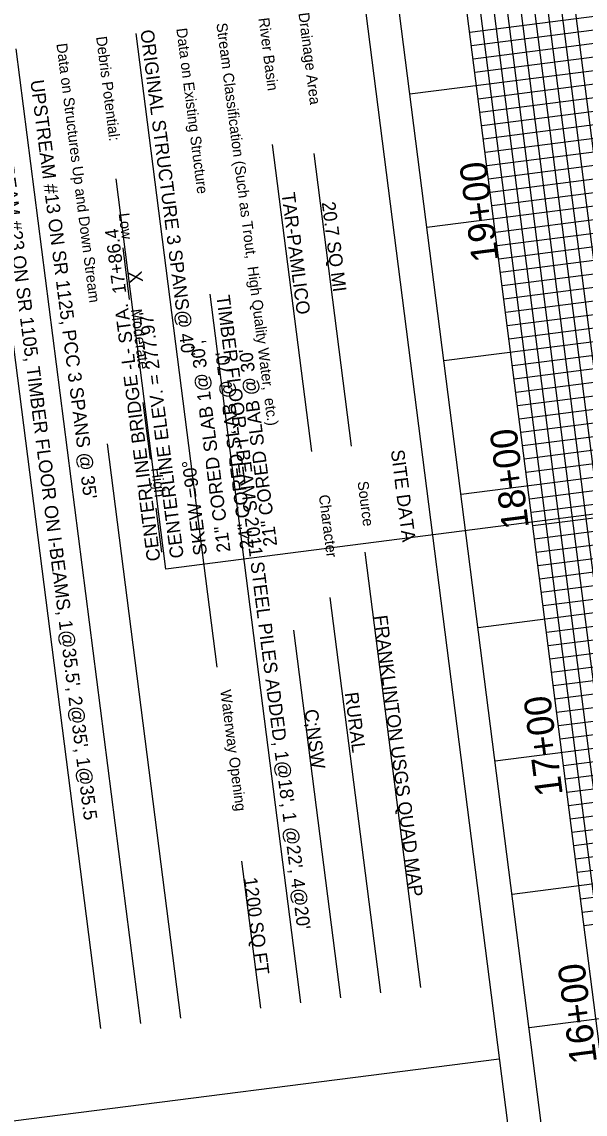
# Model space of a CAD drawing. Extents: x 2166991 to 2168413, y 842679 to 844296.
# Drawn here: x 2167468.2 to 2167677.7, y 843150.5 to 843556.7 of the extents above; entities that cross this region are included whole.
import ezdxf

# ---------------------------------------------------------------- set-up
doc = ezdxf.new("R2010")
doc.units = 0
for name, color, linetype in [('Prop Plan Preparation Cover Label', 7, 'Continuous'), ('Prop Plan Preparation Drainage Notes Label', 7, 'Continuous'), ('Prop Plan Preparation Sheet Bridge Report Limited Study CELL', 7, 'Continuous'), ('Prop Plan Preparation Station Label', 7, 'Continuous')]:
    doc.layers.add(name, color=color, linetype=linetype)

msp = doc.modelspace()

# ---------------------------------------------------------------- linework, layer by layer
at = {"layer": 'Prop Plan Preparation Drainage Notes Label'}
for p, q in [((2167521.8, 843353.19), (2167503.28, 843498.24)), ((2167765.56, 843384.32), (2167521.8, 843353.19))]:
    msp.add_line(p, q, dxfattribs=at)
at = {"layer": 'Prop Plan Preparation Sheet Bridge Report Limited Study CELL'}
for p, q in [((2167538.09, 844014.21), (2167699.63, 842749.49)), ((2167538.09, 844014.21), (2167699.63, 842749.49)), ((2167735.56, 842764.16), (2167577.19, 844004.08)), ((2167710.76, 842760.99), (2167552.39, 844000.92)), ((2167752.23, 842791.49), (2167600.19, 843981.82)), ((2167757.19, 842792.12), (2167605.15, 843982.45)), ((2167762.15, 842792.76), (2167610.11, 843983.09)), ((2167767.11, 842793.39), (2167615.07, 843983.72)), ((2167772.07, 842794.02), (2167620.03, 843984.35)), ((2167737.35, 842789.59), (2167585.31, 843979.92)), ((2167742.31, 842790.22), (2167590.27, 843980.55)), ((2167747.27, 842790.86), (2167595.23, 843981.18)), ((2168130.81, 843616.1), (2167634.84, 843552.75)), ((2168131.44, 843611.14), (2167635.47, 843547.79)), ((2168132.07, 843606.18), (2167636.1, 843542.83)), ((2168132.71, 843601.22), (2167636.74, 843537.87)), ((2168133.34, 843596.26), (2167612.57, 843529.74)), ((2168133.97, 843591.3), (2167638, 843527.95)), ((2168134.61, 843586.34), (2167638.64, 843522.99)), ((2168135.24, 843581.38), (2167639.27, 843518.03)), ((2168135.87, 843576.42), (2167639.9, 843513.07)), ((2168136.51, 843571.46), (2167640.54, 843508.11)), ((2168137.14, 843566.5), (2167641.17, 843503.15)), ((2168137.77, 843561.54), (2167641.8, 843498.19)), ((2168138.41, 843556.58), (2167642.44, 843493.23)), ((2167540.89, 843316.64), (2167510.79, 843552.29)), ((2168139.04, 843551.62), (2167643.07, 843488.27)), ((2167497.56, 843182.31), (2167451.28, 843544.69)), ((2167512.44, 843184.21), (2167466.16, 843546.59)), ((2168139.68, 843546.66), (2167618.91, 843480.15)), ((2168140.31, 843541.7), (2167644.34, 843478.35)), ((2168140.94, 843536.74), (2167644.97, 843473.39)), ((2168141.58, 843531.78), (2167645.61, 843468.43)), ((2168142.21, 843526.83), (2167646.24, 843463.47)), ((2168142.84, 843521.87), (2167646.87, 843458.52)), ((2168143.48, 843516.91), (2167647.51, 843453.56)), ((2167576.04, 843396.95), (2167561.47, 843511.05)), ((2168144.11, 843511.95), (2167648.14, 843448.6)), ((2167590.88, 843398.85), (2167576.97, 843507.77)), ((2168144.74, 843506.99), (2167648.77, 843443.64)), ((2168145.38, 843502.03), (2167649.41, 843438.68)), ((2168146.01, 843497.07), (2167625.24, 843430.55)), ((2168146.64, 843492.11), (2167650.67, 843428.76)), ((2168147.28, 843487.15), (2167651.31, 843423.8)), ((2168147.91, 843482.19), (2167651.94, 843418.84)), ((2168148.54, 843477.23), (2167652.57, 843413.88)), ((2167508.31, 843453.37), (2167505.85, 843472.59)), ((2168149.18, 843472.27), (2167653.21, 843408.92)), ((2168149.81, 843467.31), (2167653.84, 843403.96)), ((2168150.44, 843462.35), (2167654.47, 843399)), ((2167571.96, 843191.81), (2167538.29, 843455.42)), ((2168151.08, 843457.39), (2167655.11, 843394.04)), ((2168151.71, 843452.43), (2167655.74, 843389.08)), ((2168152.35, 843447.47), (2167631.58, 843380.95)), ((2168152.98, 843442.51), (2167657.01, 843379.16)), ((2168153.61, 843437.55), (2167657.64, 843374.2)), ((2168154.25, 843432.59), (2167658.28, 843369.24)), ((2168154.88, 843427.63), (2167658.91, 843364.28)), ((2168155.51, 843422.67), (2167659.54, 843359.32)), ((2168156.15, 843417.71), (2167660.18, 843354.36)), ((2167513.19, 843415.17), (2167515.89, 843393.99)), ((2168156.78, 843412.75), (2167660.81, 843349.4)), ((2168157.41, 843407.79), (2167661.44, 843344.44)), ((2168158.05, 843402.83), (2167662.08, 843339.48)), ((2167527.32, 843186.11), (2167500.04, 843399.72)), ((2168158.68, 843397.87), (2167637.91, 843331.35)), ((2168159.31, 843392.91), (2167663.34, 843329.56)), ((2168159.95, 843387.95), (2167663.98, 843324.6)), ((2168160.58, 843382.99), (2167664.61, 843319.64)), ((2168161.21, 843378.03), (2167665.24, 843314.68)), ((2167520.3, 843359.51), (2167518.21, 843375.87)), ((2168161.85, 843373.07), (2167665.88, 843309.72)), ((2168162.48, 843368.11), (2167666.51, 843304.76)), ((2168163.11, 843363.15), (2167667.14, 843299.8)), ((2167616.62, 843197.52), (2167595.94, 843359.41)), ((2168163.75, 843358.2), (2167667.78, 843294.84)), ((2168164.38, 843353.24), (2167668.41, 843289.89)), ((2168165.02, 843348.28), (2167644.25, 843281.76)), ((2167601.72, 843195.61), (2167582.94, 843342.63)), ((2168165.65, 843343.32), (2167669.68, 843279.97)), ((2168166.28, 843338.36), (2167670.31, 843275.01)), ((2168166.92, 843333.4), (2167670.95, 843270.05)), ((2167586.84, 843193.71), (2167569.37, 843330.49)), ((2168167.55, 843328.44), (2167671.58, 843265.09)), ((2168168.18, 843323.48), (2167672.21, 843260.13)), ((2168168.82, 843318.52), (2167672.85, 843255.17)), ((2168169.45, 843313.56), (2167673.48, 843250.21)), ((2168170.08, 843308.6), (2167674.11, 843245.25)), ((2168170.72, 843303.64), (2167674.75, 843240.29)), ((2168171.35, 843298.68), (2167650.58, 843232.16)), ((2168171.98, 843293.72), (2167676.01, 843230.37)), ((2168172.62, 843288.76), (2167676.65, 843225.41)), ((2168173.25, 843283.8), (2167677.28, 843220.45)), ((2168177.69, 843249.08), (2167656.92, 843182.56)), ((2167557.08, 843189.91), (2167550.1, 843244.57)), ((2167100.22, 843101.38), (2167645.78, 843171.06))]:
    msp.add_line(p, q, dxfattribs=at)

# ---------------------------------------------------------------- texts
at = {"layer": 'Prop Plan Preparation Cover Label'}
for s, p in [("ORIGINAL STRUCTURE 3 SPANS@ 40'", (2167512.28, 843553.45)), ("UPSTREAM #13 ON SR 1125, PCC 3 SPANS @ 35'  ", (2167471.37, 843534.8)), ("DOWNSTREAM #23 ON SR 1105, TIMBER FLOOR ON I-BEAMS, 1@35.5', 2@35', 1@35.5", (2167456.49, 843532.9)), ('TAR-PAMLICO', (2167564.8, 843492.89)), ('20.7 SQ MI', (2167579.78, 843489.52)), ('X', (2167507.79, 843463.69)), ("TIMBER FLOOR, I-BEAMS 2011 STEEL PILES ADDED, 1@18', 1 @22', 4@20' ", (2167540.56, 843454.79)), ('FRANKLINTON USGS QUAD MAP', (2167599.16, 843335.72)), ('RURAL', (2167588.33, 843307.09)), ('C;NSW', (2167573.33, 843300.73)), ('1200 SQ FT', (2167550.76, 843238.25))]:
    msp.add_text(s, height=5, rotation=277.279, dxfattribs=at).set_placement(p)
at = {"layer": 'Prop Plan Preparation Drainage Notes Label'}
for s, p in [('CENTERLINE BRIDGE -L- STA.  17+86.4', (2167519.8, 843356.38)), ("CENTERLINE ELEV. = 277.97'", (2167528.48, 843357.48)), ('21" CORED SLAB 1@ 30\',', (2167545.84, 843359.7)), ('24" CORED SLAB @ 70\'', (2167554.52, 843360.81)), ('21" CORED SLAB @ 30\'', (2167563.2, 843361.92)), ('SKEW =90%%d', (2167537.16, 843358.59))]:
    msp.add_text(s, height=5, rotation=97.279, dxfattribs=at).set_placement(p)
at = {"layer": 'Prop Plan Preparation Sheet Bridge Report Limited Study CELL'}
for s, height, p in [('Drainage Area', 4, (2167571.08, 843559.89)), ('Stream Classification (Such as Trout,  High Quality Water,  etc.)', 4, (2167540.57, 843556.06)), ('River Basin', 4, (2167556.24, 843557.98)), ('Data on Existing Structure', 4, (2167525.67, 843554.13)), ('Data on Structures Up and Down Stream', 4, (2167481.06, 843548.47)), ('Debris Potential:', 4, (2167495.83, 843551.05)), ('Low', 4, (2167504.22, 843485.35)), ('Moderate', 4, (2167508.78, 843449.66)), ('SITE DATA', 5, (2167605.44, 843397.29)), ('High', 4, (2167516.32, 843390.6)), ('Source', 4, (2167593.08, 843385.65)), ('Character', 4, (2167578.66, 843380.58)), ('Waterway Opening', 4, (2167542.03, 843308.06))]:
    msp.add_text(s, height=height, rotation=277.279, dxfattribs=at).set_placement(p)
at = {"layer": 'Prop Plan Preparation Station Label'}
for s, p in [('19+00', (2167645.6, 843467.97)), ('18+00', (2167656.87, 843368.68)), ('17+00', (2167669.45, 843269.34)), ('16+00', (2167682.16, 843169.8))]:
    msp.add_text(s, height=10, rotation=97.279, dxfattribs=at).set_placement(p)

doc.saveas('drawing.dxf')
